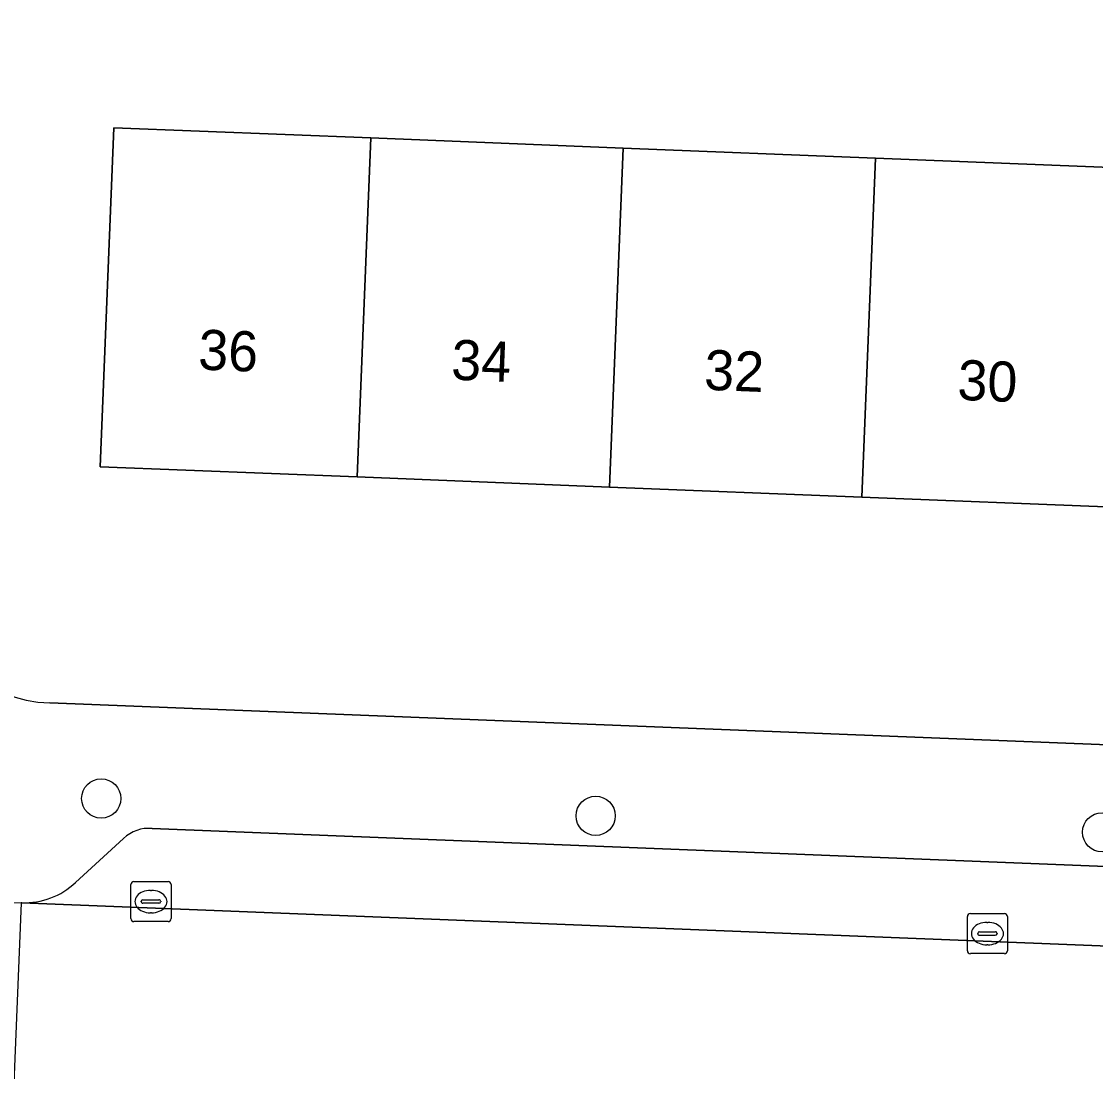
# Model space of a CAD drawing. Extents: x 160732 to 162107, y 387428 to 388479.
# Drawn here: x 161275.61 to 161302.41, y 387687.72 to 387713.9 of the extents above; entities that cross this region are included whole.
import ezdxf

# ---------------------------------------------------------------- set-up
doc = ezdxf.new("R2010")
doc.units = 0
for name, color, linetype in [('IMGEO_Boom', 7, 'Continuous'), ('IMGEO_Erf', 7, 'Continuous'), ('IMGEO_Kolk', 7, 'Continuous'), ('IMGEO_Pand', 7, 'Continuous'), ('IMGEO_Pand_nummerreeks', 7, 'Continuous'), ('IMGEO_Parkeervlak_open', 7, 'Continuous'), ('IMGEO_Rijbaan_lokaal_open', 7, 'Continuous'), ('IMGEO_Voetpad_open', 7, 'Continuous')]:
    doc.layers.add(name, color=color, linetype=linetype)

msp = doc.modelspace()

# ---------------------------------------------------------------- linework, layer by layer
at = {"layer": 'IMGEO_Boom'}
for centre in [(161277.6, 387694.524), (161289.939, 387694.092), (161302.578, 387693.682)]:
    msp.add_circle(centre, 0.489, dxfattribs=at)
at = {"layer": 'IMGEO_Erf'}
for points in [[(161276.319, 387696.913), (161355.737, 387693.76), (161355.754, 387694.392), (161356.8, 387720.356), (161354.176, 387720.544), (161354.059, 387717.756), (161350.282, 387717.915)], [(161302.874, 387701.79), (161296.579, 387702.041), (161290.285, 387702.292), (161283.99, 387702.543), (161277.576, 387702.799), (161277.914, 387711.254), (161284.328, 387710.998), (161290.623, 387710.747), (161296.917, 387710.496), (161303.212, 387710.245)]]:
    msp.add_lwpolyline(points, dxfattribs=at)
msp.add_arc((161276.341, 387699.853), 2.94, 180.0518, 269.5764, dxfattribs=at)
at = {"layer": 'IMGEO_Kolk'}
for p, q in [((161278.34, 387691.528), (161278.34, 387692.38)), ((161278.415, 387692.454), (161279.267, 387692.454)), ((161279.341, 387692.38), (161279.341, 387691.528)), ((161278.828, 387692.234), (161278.853, 387692.234)), ((161278.599, 387691.948), (161278.599, 387691.96)), ((161279.037, 387691.911), (161278.639, 387691.911)), ((161278.642, 387691.997), (161279.04, 387691.997)), ((161279.083, 387691.96), (161279.083, 387691.948)), ((161278.851, 387691.674), (161278.826, 387691.674)), ((161299.213, 387690.729), (161299.213, 387691.581)), ((161299.288, 387691.655), (161300.14, 387691.655)), ((161300.214, 387691.581), (161300.214, 387690.729)), ((161279.267, 387691.454), (161278.415, 387691.454)), ((161299.701, 387691.435), (161299.726, 387691.435)), ((161299.472, 387691.149), (161299.472, 387691.161)), ((161299.91, 387691.112), (161299.512, 387691.112)), ((161299.515, 387691.198), (161299.913, 387691.198)), ((161299.956, 387691.161), (161299.956, 387691.149)), ((161299.724, 387690.875), (161299.699, 387690.875)), ((161300.14, 387690.655), (161299.288, 387690.655))]:
    msp.add_line(p, q, dxfattribs=at)
for points in [[(161278.34, 387691.528), (161278.34, 387692.38)], [(161278.415, 387692.454), (161279.267, 387692.454)], [(161279.341, 387692.38), (161279.341, 387691.528)], [(161299.213, 387690.729), (161299.213, 387691.581)], [(161299.288, 387691.655), (161300.14, 387691.655)], [(161300.214, 387691.581), (161300.214, 387690.729)], [(161279.267, 387691.454), (161278.415, 387691.454)], [(161300.14, 387690.655), (161299.288, 387690.655)]]:
    msp.add_lwpolyline(points, dxfattribs=at)
for centre, radius, start, end in [((161278.417, 387692.378), 0.0765, 91.552, 178.448), ((161278.417, 387692.378), 0.0765, 91.552, 178.448), ((161279.265, 387692.378), 0.0765, 1.552, 88.448), ((161279.265, 387692.378), 0.0765, 1.552, 88.448), ((161278.639, 387691.957), 0.0403, 85.8775, 175.7526), ((161278.636, 387691.947), 0.0366, 178.938, 274.7102), ((161279.04, 387691.954), 0.043, 264.8664, 352.4533), ((161279.044, 387691.959), 0.0386, 1.7309, 96.639), ((161278.417, 387691.53), 0.0765, 181.552, 268.448), ((161278.417, 387691.53), 0.0765, 181.552, 268.448), ((161279.265, 387691.53), 0.0765, 271.552, 358.448), ((161279.265, 387691.53), 0.0765, 271.552, 358.448), ((161299.29, 387691.579), 0.0765, 91.552, 178.448), ((161299.29, 387691.579), 0.0765, 91.552, 178.448), ((161300.138, 387691.579), 0.0765, 1.552, 88.448), ((161300.138, 387691.579), 0.0765, 1.552, 88.448), ((161299.512, 387691.158), 0.0403, 85.8775, 175.7526), ((161299.509, 387691.148), 0.0366, 178.938, 274.7102), ((161299.913, 387691.155), 0.043, 264.8664, 352.4533), ((161299.917, 387691.16), 0.0386, 1.7309, 96.639), ((161299.29, 387690.731), 0.0765, 181.552, 268.448), ((161299.29, 387690.731), 0.0765, 181.552, 268.448), ((161300.138, 387690.731), 0.0765, 271.552, 358.448), ((161300.138, 387690.731), 0.0765, 271.552, 358.448)]:
    msp.add_arc(centre, radius, start, end, dxfattribs=at)
for centre, major_axis, ratio, start_param, end_param in [((161278.827, 387691.954), (-0.387, 0.002), 0.722429, 4.712389, 7.853982), ((161278.852, 387691.954), (-0.39, 0.002), 0.717154, 1.570796, 4.712389), ((161299.7, 387691.155), (-0.387, 0.002), 0.722429, 4.712389, 7.853982), ((161299.725, 387691.155), (-0.39, 0.002), 0.717154, 1.570796, 4.712389)]:
    msp.add_ellipse(centre, major_axis=major_axis, ratio=ratio, start_param=start_param, end_param=end_param, dxfattribs=at)
at = {"layer": 'IMGEO_Pand'}
for points in [[(161284.328, 387710.998), (161277.914, 387711.254), (161277.576, 387702.799), (161283.99, 387702.543)], [(161290.623, 387710.747), (161284.328, 387710.998), (161283.99, 387702.543), (161290.285, 387702.292)], [(161290.285, 387702.292), (161296.579, 387702.041), (161296.917, 387710.496), (161290.623, 387710.747)], [(161296.579, 387702.041), (161302.874, 387701.79), (161303.212, 387710.245), (161296.917, 387710.496)]]:
    msp.add_lwpolyline(points, close=True, dxfattribs=at)
at = {"layer": 'IMGEO_Parkeervlak_open'}
for points in [[(161351.318, 387690.889), (161278.871, 387693.776)], [(161278.155, 387693.528), (161276.961, 387692.432)], [(161275.618, 387691.924), (161347.168, 387689.072)]]:
    msp.add_lwpolyline(points, dxfattribs=at)
for centre, radius, start, end in [((161278.784, 387692.869), 0.911, 84.5234, 133.6856), ((161275.682, 387693.783), 1.86, 268.0154, 313.4236)]:
    msp.add_arc(centre, radius, start, end, dxfattribs=at)
at = {"layer": 'IMGEO_Rijbaan_lokaal_open'}
msp.add_lwpolyline([(161347.168, 387689.072), (161275.618, 387691.924), (161275.601, 387691.925), (161275.404, 387687.021), (161286.329, 387686.613), (161305.921, 387685.824), (161347.031, 387684.145)], close=True, dxfattribs=at)
at = {"layer": 'IMGEO_Voetpad_open'}
for points in [[(161424.249, 387690.975), (161423.165, 387691.018), (161402.729, 387691.836), (161401.241, 387691.896), (161360.471, 387693.53), (161355.737, 387693.76), (161276.319, 387696.913)], [(161278.871, 387693.776), (161351.318, 387690.889)], [(161276.961, 387692.432), (161278.155, 387693.528)], [(161274.312, 387691.973), (161275.601, 387691.925), (161275.618, 387691.924)]]:
    msp.add_lwpolyline(points, dxfattribs=at)
for centre, radius, start, end in [((161276.341, 387699.853), 2.94, 180.0518, 269.5764), ((161278.784, 387692.869), 0.911, 84.5234, 133.6856), ((161275.682, 387693.783), 1.86, 268.0154, 313.4236)]:
    msp.add_arc(centre, radius, start, end, dxfattribs=at)

# ---------------------------------------------------------------- texts
at = {"layer": 'IMGEO_Pand_nummerreeks'}
for s, p in [('36', (161280.008, 387705.224)), ('34', (161286.322, 387704.972)), ('32', (161292.634, 387704.72)), ('30', (161298.954, 387704.468))]:
    msp.add_text(s, height=1, rotation=357.7154, dxfattribs=at).set_placement(p)

doc.saveas('drawing.dxf')
